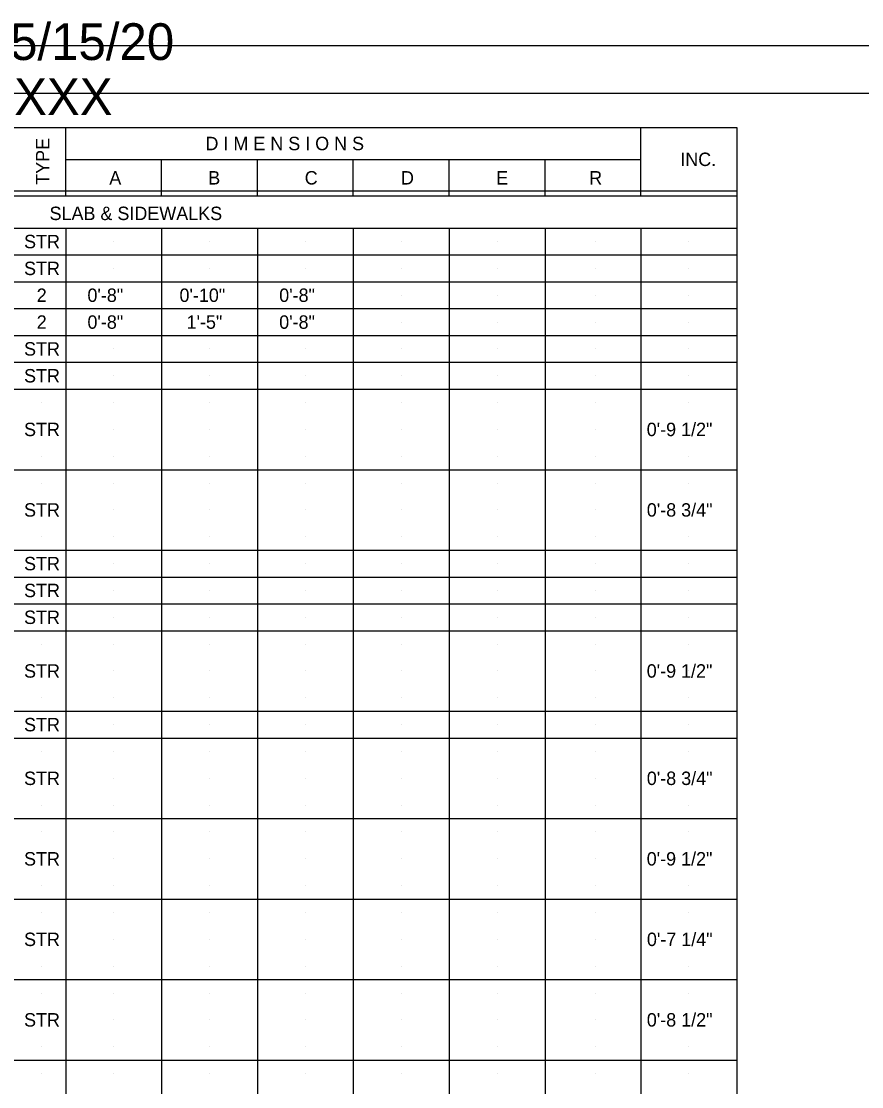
# Model space of a CAD drawing. Extents: x -31.1 to 2.9, y 8.5 to 31.4.
# Drawn here: x -23.78 to -15.02, y 19.62 to 30.73 of the extents above; entities that cross this region are included whole.
import ezdxf

# ---------------------------------------------------------------- set-up
doc = ezdxf.new("R2010")
doc.units = 0
for name, color, linetype in [('BR_P_Gen_Text', 7, 'Continuous'), ('Default', 7, 'Continuous'), ('SC_Scratch1', 7, 'Continuous'), ('SC_Scratch2', 7, 'Continuous')]:
    doc.layers.add(name, color=color, linetype=linetype)

msp = doc.modelspace()

# ---------------------------------------------------------------- linework, layer by layer
at = {"layer": 'BR_P_Gen_Text'}
for p, q in [((-28.487, 29.627), (-16.32, 29.627)), ((-23.32, 28.91), (-23.32, 29.627)), ((-17.32, 28.91), (-17.32, 29.627)), ((-16.32, 29.627), (-16.32, 13.737)), ((-23.32, 29.294), (-17.32, 29.294)), ((-22.32, 28.91), (-22.32, 29.294)), ((-21.32, 28.91), (-21.32, 29.294)), ((-20.32, 28.91), (-20.32, 29.294)), ((-19.32, 28.91), (-19.32, 29.294)), ((-18.32, 28.91), (-18.32, 29.294)), ((-16.32, 28.962), (-28.487, 28.962)), ((-17.665, 28.91), (-28.487, 28.91)), ((-16.32, 28.91), (-28.487, 28.91)), ((-28.487, 28.577), (-16.32, 28.577)), ((-23.32, 28.577), (-23.32, 13.737)), ((-22.32, 28.577), (-22.32, 13.737)), ((-21.32, 28.577), (-21.32, 13.737)), ((-20.32, 28.577), (-20.32, 13.737)), ((-19.32, 28.577), (-19.32, 13.737)), ((-18.32, 28.577), (-18.32, 13.737)), ((-17.32, 28.577), (-17.32, 13.737)), ((-28.487, 28.297), (-16.32, 28.297)), ((-28.487, 28.017), (-16.32, 28.017)), ((-28.487, 27.737), (-16.32, 27.737)), ((-28.487, 27.457), (-16.32, 27.457)), ((-28.487, 27.177), (-16.32, 27.177)), ((-28.487, 26.897), (-16.32, 26.897)), ((-28.487, 26.057), (-16.32, 26.057)), ((-28.487, 25.217), (-16.32, 25.217)), ((-28.487, 24.937), (-16.32, 24.937)), ((-28.487, 24.657), (-16.32, 24.657)), ((-28.487, 24.377), (-16.32, 24.377)), ((-28.487, 23.537), (-16.32, 23.537)), ((-28.487, 23.257), (-16.32, 23.257)), ((-28.487, 22.417), (-16.32, 22.417)), ((-28.487, 21.577), (-16.32, 21.577)), ((-28.487, 20.737), (-16.32, 20.737)), ((-28.487, 19.897), (-16.32, 19.897))]:
    msp.add_line(p, q, dxfattribs=at)
for points in [[(-31.128, 30.484), (2.872, 30.484), (2.872, 8.484), (-31.128, 8.484)], [(-29.128, 29.984), (1.372, 29.984), (1.372, 8.984), (-29.128, 8.984)]]:
    msp.add_lwpolyline(points, close=True, dxfattribs=at)
at = {"layer": 'SC_Scratch1'}
for p, q in [((-23.57, 28.437), (-23.57, 28.437)), ((-22.82, 28.437), (-22.82, 28.437)), ((-21.82, 28.437), (-21.82, 28.437)), ((-20.82, 28.437), (-20.82, 28.437)), ((-19.82, 28.437), (-19.82, 28.437)), ((-18.82, 28.437), (-18.82, 28.437)), ((-17.797, 28.437), (-17.797, 28.437)), ((-16.82, 28.437), (-16.82, 28.437)), ((-23.57, 28.157), (-23.57, 28.157)), ((-22.82, 28.157), (-22.82, 28.157)), ((-21.82, 28.157), (-21.82, 28.157)), ((-20.82, 28.157), (-20.82, 28.157)), ((-19.82, 28.157), (-19.82, 28.157)), ((-18.82, 28.157), (-18.82, 28.157)), ((-17.797, 28.157), (-17.797, 28.157)), ((-16.82, 28.157), (-16.82, 28.157)), ((-23.57, 27.877), (-23.57, 27.877)), ((-22.82, 27.877), (-22.82, 27.877)), ((-21.82, 27.877), (-21.82, 27.877)), ((-20.82, 27.877), (-20.82, 27.877)), ((-19.82, 27.877), (-19.82, 27.877)), ((-18.82, 27.877), (-18.82, 27.877)), ((-17.797, 27.877), (-17.797, 27.877)), ((-16.82, 27.877), (-16.82, 27.877)), ((-23.57, 27.597), (-23.57, 27.597)), ((-22.82, 27.597), (-22.82, 27.597)), ((-21.82, 27.597), (-21.82, 27.597)), ((-20.82, 27.597), (-20.82, 27.597)), ((-19.82, 27.597), (-19.82, 27.597)), ((-18.82, 27.597), (-18.82, 27.597)), ((-17.797, 27.597), (-17.797, 27.597)), ((-16.82, 27.597), (-16.82, 27.597)), ((-23.57, 27.317), (-23.57, 27.317)), ((-22.82, 27.317), (-22.82, 27.317)), ((-21.82, 27.317), (-21.82, 27.317)), ((-20.82, 27.317), (-20.82, 27.317)), ((-19.82, 27.317), (-19.82, 27.317)), ((-18.82, 27.317), (-18.82, 27.317)), ((-17.797, 27.317), (-17.797, 27.317)), ((-16.82, 27.317), (-16.82, 27.317)), ((-23.57, 27.037), (-23.57, 27.037)), ((-22.82, 27.037), (-22.82, 27.037)), ((-21.82, 27.037), (-21.82, 27.037)), ((-20.82, 27.037), (-20.82, 27.037)), ((-19.82, 27.037), (-19.82, 27.037)), ((-18.82, 27.037), (-18.82, 27.037)), ((-17.797, 27.037), (-17.797, 27.037)), ((-16.82, 27.037), (-16.82, 27.037)), ((-23.57, 26.757), (-23.57, 26.757)), ((-22.82, 26.757), (-22.82, 26.757)), ((-21.82, 26.757), (-21.82, 26.757)), ((-20.82, 26.757), (-20.82, 26.757)), ((-19.82, 26.757), (-19.82, 26.757)), ((-18.82, 26.757), (-18.82, 26.757)), ((-17.797, 26.757), (-17.797, 26.757)), ((-16.82, 26.757), (-16.82, 26.757)), ((-23.57, 26.477), (-23.57, 26.477)), ((-22.82, 26.477), (-22.82, 26.477)), ((-21.82, 26.477), (-21.82, 26.477)), ((-20.82, 26.477), (-20.82, 26.477)), ((-19.82, 26.477), (-19.82, 26.477)), ((-18.82, 26.477), (-18.82, 26.477)), ((-17.797, 26.477), (-17.797, 26.477)), ((-16.82, 26.477), (-16.82, 26.477)), ((-23.57, 26.197), (-23.57, 26.197)), ((-22.82, 26.197), (-22.82, 26.197)), ((-21.82, 26.197), (-21.82, 26.197)), ((-20.82, 26.197), (-20.82, 26.197)), ((-19.82, 26.197), (-19.82, 26.197)), ((-18.82, 26.197), (-18.82, 26.197)), ((-17.797, 26.197), (-17.797, 26.197)), ((-16.82, 26.197), (-16.82, 26.197)), ((-23.57, 25.917), (-23.57, 25.917)), ((-22.82, 25.917), (-22.82, 25.917)), ((-21.82, 25.917), (-21.82, 25.917)), ((-20.82, 25.917), (-20.82, 25.917)), ((-19.82, 25.917), (-19.82, 25.917)), ((-18.82, 25.917), (-18.82, 25.917)), ((-17.797, 25.917), (-17.797, 25.917)), ((-16.82, 25.917), (-16.82, 25.917)), ((-23.57, 25.637), (-23.57, 25.637)), ((-22.82, 25.637), (-22.82, 25.637)), ((-21.82, 25.637), (-21.82, 25.637)), ((-20.82, 25.637), (-20.82, 25.637)), ((-19.82, 25.637), (-19.82, 25.637)), ((-18.82, 25.637), (-18.82, 25.637)), ((-17.797, 25.637), (-17.797, 25.637)), ((-16.82, 25.637), (-16.82, 25.637)), ((-23.57, 25.357), (-23.57, 25.357)), ((-22.82, 25.357), (-22.82, 25.357)), ((-21.82, 25.357), (-21.82, 25.357)), ((-20.82, 25.357), (-20.82, 25.357)), ((-19.82, 25.357), (-19.82, 25.357)), ((-18.82, 25.357), (-18.82, 25.357)), ((-17.797, 25.357), (-17.797, 25.357)), ((-16.82, 25.357), (-16.82, 25.357)), ((-23.57, 25.077), (-23.57, 25.077)), ((-22.82, 25.077), (-22.82, 25.077)), ((-21.82, 25.077), (-21.82, 25.077)), ((-20.82, 25.077), (-20.82, 25.077)), ((-19.82, 25.077), (-19.82, 25.077)), ((-18.82, 25.077), (-18.82, 25.077)), ((-17.797, 25.077), (-17.797, 25.077)), ((-16.82, 25.077), (-16.82, 25.077)), ((-23.57, 24.797), (-23.57, 24.797)), ((-22.82, 24.797), (-22.82, 24.797)), ((-21.82, 24.797), (-21.82, 24.797)), ((-20.82, 24.797), (-20.82, 24.797)), ((-19.82, 24.797), (-19.82, 24.797)), ((-18.82, 24.797), (-18.82, 24.797)), ((-17.797, 24.797), (-17.797, 24.797)), ((-16.82, 24.797), (-16.82, 24.797)), ((-23.57, 24.517), (-23.57, 24.517)), ((-22.82, 24.517), (-22.82, 24.517)), ((-21.82, 24.517), (-21.82, 24.517)), ((-20.82, 24.517), (-20.82, 24.517)), ((-19.82, 24.517), (-19.82, 24.517)), ((-18.82, 24.517), (-18.82, 24.517)), ((-17.797, 24.517), (-17.797, 24.517)), ((-16.82, 24.517), (-16.82, 24.517)), ((-23.57, 24.237), (-23.57, 24.237)), ((-22.82, 24.237), (-22.82, 24.237)), ((-21.82, 24.237), (-21.82, 24.237)), ((-20.82, 24.237), (-20.82, 24.237)), ((-19.82, 24.237), (-19.82, 24.237)), ((-18.82, 24.237), (-18.82, 24.237)), ((-17.797, 24.237), (-17.797, 24.237)), ((-16.82, 24.237), (-16.82, 24.237)), ((-23.57, 23.957), (-23.57, 23.957)), ((-22.82, 23.957), (-22.82, 23.957)), ((-21.82, 23.957), (-21.82, 23.957)), ((-20.82, 23.957), (-20.82, 23.957)), ((-19.82, 23.957), (-19.82, 23.957)), ((-18.82, 23.957), (-18.82, 23.957)), ((-17.797, 23.957), (-17.797, 23.957)), ((-16.82, 23.957), (-16.82, 23.957)), ((-23.57, 23.677), (-23.57, 23.677)), ((-22.82, 23.677), (-22.82, 23.677)), ((-21.82, 23.677), (-21.82, 23.677)), ((-20.82, 23.677), (-20.82, 23.677)), ((-19.82, 23.677), (-19.82, 23.677)), ((-18.82, 23.677), (-18.82, 23.677)), ((-17.797, 23.677), (-17.797, 23.677)), ((-16.82, 23.677), (-16.82, 23.677)), ((-23.57, 23.397), (-23.57, 23.397)), ((-22.82, 23.397), (-22.82, 23.397)), ((-21.82, 23.397), (-21.82, 23.397)), ((-20.82, 23.397), (-20.82, 23.397)), ((-19.82, 23.397), (-19.82, 23.397)), ((-18.82, 23.397), (-18.82, 23.397)), ((-17.797, 23.397), (-17.797, 23.397)), ((-16.82, 23.397), (-16.82, 23.397)), ((-23.57, 23.117), (-23.57, 23.117)), ((-22.82, 23.117), (-22.82, 23.117)), ((-21.82, 23.117), (-21.82, 23.117)), ((-20.82, 23.117), (-20.82, 23.117)), ((-19.82, 23.117), (-19.82, 23.117)), ((-18.82, 23.117), (-18.82, 23.117)), ((-17.797, 23.117), (-17.797, 23.117)), ((-16.82, 23.117), (-16.82, 23.117)), ((-23.57, 22.837), (-23.57, 22.837)), ((-22.82, 22.837), (-22.82, 22.837)), ((-21.82, 22.837), (-21.82, 22.837)), ((-20.82, 22.837), (-20.82, 22.837)), ((-19.82, 22.837), (-19.82, 22.837)), ((-18.82, 22.837), (-18.82, 22.837)), ((-17.797, 22.837), (-17.797, 22.837)), ((-16.82, 22.837), (-16.82, 22.837)), ((-23.57, 22.557), (-23.57, 22.557)), ((-22.82, 22.557), (-22.82, 22.557)), ((-21.82, 22.557), (-21.82, 22.557)), ((-20.82, 22.557), (-20.82, 22.557)), ((-19.82, 22.557), (-19.82, 22.557)), ((-18.82, 22.557), (-18.82, 22.557)), ((-17.797, 22.557), (-17.797, 22.557)), ((-16.82, 22.557), (-16.82, 22.557)), ((-23.57, 22.277), (-23.57, 22.277)), ((-22.82, 22.277), (-22.82, 22.277)), ((-21.82, 22.277), (-21.82, 22.277)), ((-20.82, 22.277), (-20.82, 22.277)), ((-19.82, 22.277), (-19.82, 22.277)), ((-18.82, 22.277), (-18.82, 22.277)), ((-17.797, 22.277), (-17.797, 22.277)), ((-16.82, 22.277), (-16.82, 22.277)), ((-23.57, 21.997), (-23.57, 21.997)), ((-22.82, 21.997), (-22.82, 21.997)), ((-21.82, 21.997), (-21.82, 21.997)), ((-20.82, 21.997), (-20.82, 21.997)), ((-19.82, 21.997), (-19.82, 21.997)), ((-18.82, 21.997), (-18.82, 21.997)), ((-17.797, 21.997), (-17.797, 21.997)), ((-16.82, 21.997), (-16.82, 21.997)), ((-23.57, 21.717), (-23.57, 21.717)), ((-22.82, 21.717), (-22.82, 21.717)), ((-21.82, 21.717), (-21.82, 21.717)), ((-20.82, 21.717), (-20.82, 21.717)), ((-19.82, 21.717), (-19.82, 21.717)), ((-18.82, 21.717), (-18.82, 21.717)), ((-17.797, 21.717), (-17.797, 21.717)), ((-16.82, 21.717), (-16.82, 21.717)), ((-23.57, 21.437), (-23.57, 21.437)), ((-22.82, 21.437), (-22.82, 21.437)), ((-21.82, 21.437), (-21.82, 21.437)), ((-20.82, 21.437), (-20.82, 21.437)), ((-19.82, 21.437), (-19.82, 21.437)), ((-18.82, 21.437), (-18.82, 21.437)), ((-17.797, 21.437), (-17.797, 21.437)), ((-16.82, 21.437), (-16.82, 21.437)), ((-23.57, 21.157), (-23.57, 21.157)), ((-22.82, 21.157), (-22.82, 21.157)), ((-21.82, 21.157), (-21.82, 21.157)), ((-20.82, 21.157), (-20.82, 21.157)), ((-19.82, 21.157), (-19.82, 21.157)), ((-18.82, 21.157), (-18.82, 21.157)), ((-17.797, 21.157), (-17.797, 21.157)), ((-16.82, 21.157), (-16.82, 21.157)), ((-23.57, 20.877), (-23.57, 20.877)), ((-22.82, 20.877), (-22.82, 20.877)), ((-21.82, 20.877), (-21.82, 20.877)), ((-20.82, 20.877), (-20.82, 20.877)), ((-19.82, 20.877), (-19.82, 20.877)), ((-18.82, 20.877), (-18.82, 20.877)), ((-17.797, 20.877), (-17.797, 20.877)), ((-16.82, 20.877), (-16.82, 20.877)), ((-23.57, 20.597), (-23.57, 20.597)), ((-22.82, 20.597), (-22.82, 20.597)), ((-21.82, 20.597), (-21.82, 20.597)), ((-20.82, 20.597), (-20.82, 20.597)), ((-19.82, 20.597), (-19.82, 20.597)), ((-18.82, 20.597), (-18.82, 20.597)), ((-17.797, 20.597), (-17.797, 20.597)), ((-16.82, 20.597), (-16.82, 20.597)), ((-23.57, 20.317), (-23.57, 20.317)), ((-22.82, 20.317), (-22.82, 20.317)), ((-21.82, 20.317), (-21.82, 20.317)), ((-20.82, 20.317), (-20.82, 20.317)), ((-19.82, 20.317), (-19.82, 20.317)), ((-18.82, 20.317), (-18.82, 20.317)), ((-17.797, 20.317), (-17.797, 20.317)), ((-16.82, 20.317), (-16.82, 20.317)), ((-23.57, 20.037), (-23.57, 20.037)), ((-22.82, 20.037), (-22.82, 20.037)), ((-21.82, 20.037), (-21.82, 20.037)), ((-20.82, 20.037), (-20.82, 20.037)), ((-19.82, 20.037), (-19.82, 20.037)), ((-18.82, 20.037), (-18.82, 20.037)), ((-17.797, 20.037), (-17.797, 20.037)), ((-16.82, 20.037), (-16.82, 20.037)), ((-23.57, 19.757), (-23.57, 19.757)), ((-22.82, 19.757), (-22.82, 19.757)), ((-21.82, 19.757), (-21.82, 19.757)), ((-20.82, 19.757), (-20.82, 19.757)), ((-19.82, 19.757), (-19.82, 19.757)), ((-18.82, 19.757), (-18.82, 19.757)), ((-17.797, 19.757), (-17.797, 19.757)), ((-16.82, 19.757), (-16.82, 19.757))]:
    msp.add_line(p, q, dxfattribs=at)

# ---------------------------------------------------------------- texts
at = {"layer": 'BR_P_Gen_Text'}
for s, p in [('STR', (-23.754, 28.367)), ('STR', (-23.754, 28.087)), ('2', (-23.622, 27.807)), ('0\'-8"', (-23.093, 27.807)), ('0\'-10"', (-22.133, 27.807)), ('0\'-8"', (-21.093, 27.807)), ('2', (-23.622, 27.527)), ('0\'-8"', (-23.093, 27.527)), ('1\'-5"', (-22.059, 27.527)), ('0\'-8"', (-21.093, 27.527)), ('STR', (-23.754, 27.247)), ('STR', (-23.754, 26.967)), ('STR', (-23.754, 26.407)), ('0\'-9 1/2"', (-17.26, 26.407)), ('STR', (-23.754, 25.567)), ('0\'-8 3/4"', (-17.259, 25.567)), ('STR', (-23.754, 25.007)), ('STR', (-23.754, 24.727)), ('STR', (-23.754, 24.447)), ('STR', (-23.754, 23.887)), ('0\'-9 1/2"', (-17.26, 23.887)), ('STR', (-23.754, 23.327)), ('STR', (-23.754, 22.767)), ('0\'-8 3/4"', (-17.259, 22.767)), ('STR', (-23.754, 21.927)), ('0\'-9 1/2"', (-17.26, 21.927)), ('0\'-7 1/4"', (-17.258, 21.087)), ('STR', (-23.754, 21.087)), ('STR', (-23.754, 20.247)), ('0\'-8 1/2"', (-17.259, 20.247))]:
    msp.add_text(s, height=0.14, dxfattribs=at).set_placement(p)
at = {"layer": 'Default'}
msp.add_text('TYPE', height=0.14, rotation=90, dxfattribs=at).set_placement((-23.49, 29.029))
for s, p in [('D I M E N S I O N S', (-21.862, 29.39)), ('INC.', (-16.91, 29.225)), ('A', (-22.865, 29.032)), ('B', (-21.833, 29.032)), ('C', (-20.827, 29.032)), ('D', (-19.823, 29.032)), ('E', (-18.83, 29.032)), ('R', (-17.86, 29.032)), ('SLAB & SIDEWALKS', (-23.488, 28.661))]:
    msp.add_text(s, height=0.14, dxfattribs=at).set_placement(p)
at = {"layer": 'SC_Scratch2'}
for s, p in [('DESIGNED BY RFV 5/15/20', (-28.714, 30.331)), ('CHECKED BY XXX', (-27.333, 29.756))]:
    msp.add_text(s, height=0.38343, dxfattribs=at).set_placement(p)

doc.saveas('drawing.dxf')
